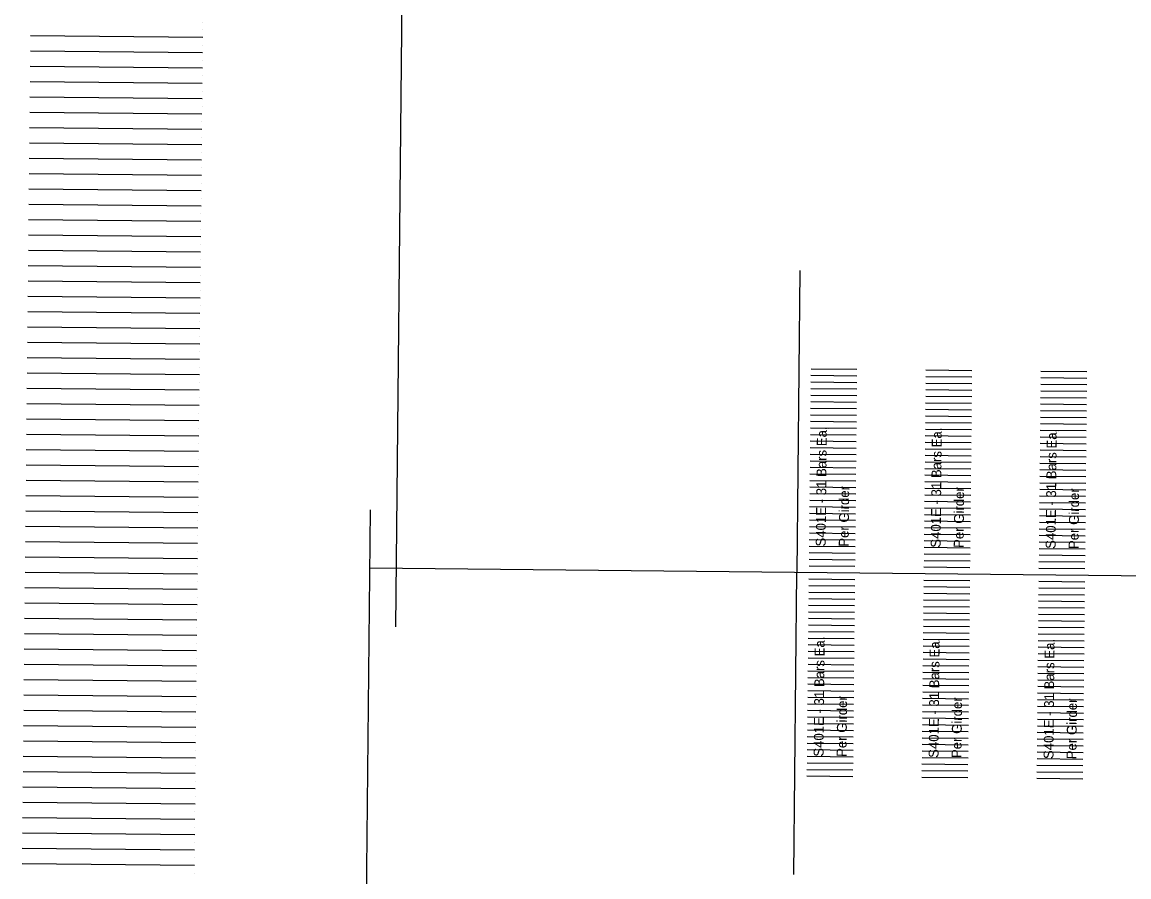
# Model space of a CAD drawing. Extents: x 632547 to 633311, y 380830 to 386139.
# Drawn here: x 633071.5 to 633155.8, y 381137.1 to 381202.2 of the extents above; entities that cross this region are included whole.
import ezdxf

# ---------------------------------------------------------------- set-up
doc = ezdxf.new("R2010")
doc.units = 0
for name, color, linetype in [('B_Border', 7, 'Continuous'), ('R_Border_Scale', 7, 'Continuous'), ('R_Wall', 7, 'Continuous')]:
    doc.layers.add(name, color=color, linetype=linetype)

msp = doc.modelspace()

# ---------------------------------------------------------------- linework, layer by layer
at = {"layer": 'B_Border'}
msp.add_line((633215.055, 381159.402), (633098.001, 381160.586), dxfattribs=at)
at = {"layer": 'R_Border_Scale'}
for p, q in [((633100.563, 381216.118), (633099.956, 381156.121)), ((633085.309, 381202.16), (633085.309, 381202.16)), ((633085.297, 381200.993), (633072.186, 381201.125)), ((633085.297, 381200.993), (633085.297, 381200.993)), ((633085.303, 381201.576), (633085.303, 381201.576)), ((633085.291, 381200.409), (633085.291, 381200.409)), ((633085.286, 381199.825), (633072.174, 381199.958)), ((633085.286, 381199.825), (633085.286, 381199.825)), ((633085.274, 381198.658), (633072.163, 381198.79)), ((633085.274, 381198.658), (633085.274, 381198.658)), ((633085.28, 381199.241), (633085.28, 381199.241)), ((633085.262, 381197.49), (633072.151, 381197.623)), ((633085.268, 381198.074), (633085.268, 381198.074)), ((633085.256, 381196.907), (633085.256, 381196.907)), ((633085.262, 381197.49), (633085.262, 381197.49)), ((633085.25, 381196.323), (633072.139, 381196.456)), ((633085.25, 381196.323), (633085.25, 381196.323)), ((633085.238, 381195.156), (633072.127, 381195.288)), ((633085.238, 381195.156), (633085.238, 381195.156)), ((633085.244, 381195.739), (633085.244, 381195.739)), ((633085.232, 381194.572), (633085.232, 381194.572)), ((633085.226, 381193.988), (633072.115, 381194.121)), ((633085.221, 381193.405), (633085.221, 381193.405)), ((633085.226, 381193.988), (633085.226, 381193.988)), ((633085.215, 381192.821), (633072.103, 381192.954)), ((633085.215, 381192.821), (633085.215, 381192.821)), ((633085.203, 381191.654), (633072.092, 381191.786)), ((633085.209, 381192.237), (633085.209, 381192.237)), ((633085.197, 381191.07), (633085.197, 381191.07)), ((633085.203, 381191.654), (633085.203, 381191.654)), ((633085.191, 381190.486), (633072.08, 381190.619)), ((633085.191, 381190.486), (633085.191, 381190.486)), ((633085.179, 381189.319), (633072.068, 381189.452)), ((633085.179, 381189.319), (633085.179, 381189.319)), ((633085.185, 381189.903), (633085.185, 381189.903)), ((633085.173, 381188.735), (633085.173, 381188.735)), ((633085.167, 381188.152), (633072.056, 381188.284)), ((633085.161, 381187.568), (633085.161, 381187.568)), ((633085.167, 381188.152), (633085.167, 381188.152)), ((633085.156, 381186.984), (633072.044, 381187.117)), ((633085.156, 381186.984), (633085.156, 381186.984)), ((633085.144, 381185.817), (633072.033, 381185.95)), ((633085.144, 381185.817), (633085.144, 381185.817)), ((633085.15, 381186.401), (633085.15, 381186.401)), ((633085.138, 381185.233), (633085.138, 381185.233)), ((633085.132, 381184.65), (633072.021, 381184.782)), ((633085.132, 381184.65), (633085.132, 381184.65)), ((633085.12, 381183.482), (633072.009, 381183.615)), ((633085.12, 381183.482), (633085.12, 381183.482)), ((633085.126, 381184.066), (633085.126, 381184.066)), ((633085.108, 381182.315), (633071.997, 381182.447)), ((633085.114, 381182.898), (633085.114, 381182.898)), ((633130.736, 381183.256), (633130.503, 381160.257)), ((633085.102, 381181.731), (633085.102, 381181.731)), ((633085.108, 381182.315), (633085.108, 381182.315)), ((633085.097, 381181.147), (633071.985, 381181.28)), ((633085.097, 381181.147), (633085.097, 381181.147)), ((633085.085, 381179.98), (633071.974, 381180.113)), ((633085.085, 381179.98), (633085.085, 381179.98)), ((633085.091, 381180.564), (633085.091, 381180.564)), ((633085.079, 381179.396), (633085.079, 381179.396)), ((633085.073, 381178.813), (633071.962, 381178.945)), ((633085.073, 381178.813), (633085.073, 381178.813)), ((633085.061, 381177.645), (633071.95, 381177.778)), ((633085.061, 381177.645), (633085.061, 381177.645)), ((633085.067, 381178.229), (633085.067, 381178.229)), ((633085.049, 381176.478), (633071.938, 381176.611)), ((633085.055, 381177.062), (633085.055, 381177.062)), ((633085.043, 381175.894), (633085.043, 381175.894)), ((633085.049, 381176.478), (633085.049, 381176.478)), ((633135.091, 381175.712), (633131.591, 381175.747)), ((633085.037, 381175.311), (633071.926, 381175.443)), ((633085.037, 381175.311), (633085.037, 381175.311)), ((633135.086, 381175.212), (633131.586, 381175.247)), ((633143.835, 381175.123), (633140.335, 381175.159)), ((633143.84, 381175.623), (633140.341, 381175.659)), ((633152.585, 381175.035), (633149.085, 381175.07)), ((633152.59, 381175.535), (633149.09, 381175.57)), ((633085.026, 381174.143), (633071.915, 381174.276)), ((633085.026, 381174.143), (633085.026, 381174.143)), ((633085.032, 381174.727), (633085.032, 381174.727)), ((633135.076, 381174.212), (633131.576, 381174.247)), ((633135.081, 381174.712), (633131.581, 381174.747)), ((633143.825, 381174.123), (633140.325, 381174.159)), ((633143.83, 381174.623), (633140.33, 381174.659)), ((633152.575, 381174.035), (633149.075, 381174.07)), ((633152.58, 381174.535), (633149.08, 381174.57)), ((633085.02, 381173.56), (633085.02, 381173.56)), ((633135.065, 381173.212), (633131.566, 381173.247)), ((633135.071, 381173.712), (633131.571, 381173.747)), ((633143.82, 381173.623), (633140.32, 381173.659)), ((633152.57, 381173.535), (633149.07, 381173.57)), ((633085.014, 381172.976), (633071.903, 381173.109)), ((633085.008, 381172.392), (633085.008, 381172.392)), ((633085.014, 381172.976), (633085.014, 381172.976)), ((633135.06, 381172.712), (633131.561, 381172.747)), ((633143.81, 381172.623), (633140.31, 381172.659)), ((633143.815, 381173.123), (633140.315, 381173.159)), ((633152.56, 381172.535), (633149.06, 381172.57)), ((633152.565, 381173.035), (633149.065, 381173.07)), ((633085.002, 381171.809), (633071.891, 381171.941)), ((633085.002, 381171.809), (633085.002, 381171.809)), ((633135.05, 381171.712), (633131.55, 381171.747)), ((633135.055, 381172.212), (633131.556, 381172.247)), ((633143.8, 381171.623), (633140.3, 381171.659)), ((633143.805, 381172.123), (633140.305, 381172.159)), ((633152.549, 381171.535), (633149.05, 381171.57)), ((633152.554, 381172.035), (633149.055, 381172.07)), ((633084.99, 381170.641), (633071.879, 381170.774)), ((633084.996, 381171.225), (633084.996, 381171.225)), ((633135.04, 381170.712), (633131.54, 381170.747)), ((633135.045, 381171.212), (633131.545, 381171.247)), ((633143.79, 381170.623), (633140.29, 381170.659)), ((633143.795, 381171.123), (633140.295, 381171.159)), ((633152.544, 381171.035), (633149.045, 381171.07)), ((633084.984, 381170.058), (633084.984, 381170.058)), ((633084.99, 381170.641), (633084.99, 381170.641)), ((633135.035, 381170.212), (633131.535, 381170.247)), ((633143.785, 381170.123), (633140.285, 381170.159)), ((633152.534, 381170.035), (633149.034, 381170.07)), ((633152.539, 381170.535), (633149.039, 381170.57)), ((633084.978, 381169.474), (633071.867, 381169.607)), ((633084.978, 381169.474), (633084.978, 381169.474)), ((633135.025, 381169.212), (633131.525, 381169.247)), ((633135.03, 381169.712), (633131.53, 381169.747)), ((633143.775, 381169.123), (633140.275, 381169.159)), ((633143.78, 381169.623), (633140.28, 381169.659)), ((633152.524, 381169.035), (633149.024, 381169.07)), ((633152.529, 381169.535), (633149.029, 381169.57)), ((633084.967, 381168.307), (633071.855, 381168.439)), ((633084.967, 381168.307), (633084.967, 381168.307)), ((633084.973, 381168.89), (633084.973, 381168.89)), ((633135.015, 381168.212), (633131.515, 381168.247)), ((633135.02, 381168.712), (633131.52, 381168.747)), ((633143.764, 381168.123), (633140.265, 381168.159)), ((633143.77, 381168.623), (633140.27, 381168.659)), ((633152.519, 381168.535), (633149.019, 381168.57)), ((633084.961, 381167.723), (633084.961, 381167.723)), ((633135.01, 381167.712), (633131.51, 381167.747)), ((633143.759, 381167.624), (633140.26, 381167.659)), ((633152.509, 381167.535), (633149.009, 381167.57)), ((633152.514, 381168.035), (633149.014, 381168.07)), ((633084.955, 381167.139), (633071.844, 381167.272)), ((633084.949, 381166.556), (633084.949, 381166.556)), ((633084.955, 381167.139), (633084.955, 381167.139)), ((633135, 381166.712), (633131.5, 381166.748)), ((633135.005, 381167.212), (633131.505, 381167.247)), ((633143.749, 381166.624), (633140.249, 381166.659)), ((633143.754, 381167.124), (633140.255, 381167.159)), ((633152.499, 381166.535), (633148.999, 381166.57)), ((633152.504, 381167.035), (633149.004, 381167.07)), ((633084.943, 381165.972), (633071.832, 381166.104)), ((633084.943, 381165.972), (633084.943, 381165.972)), ((633134.99, 381165.712), (633131.49, 381165.748)), ((633134.995, 381166.212), (633131.495, 381166.248)), ((633143.739, 381165.624), (633140.239, 381165.659)), ((633143.744, 381166.124), (633140.244, 381166.159)), ((633152.494, 381166.035), (633148.994, 381166.07)), ((633084.931, 381164.804), (633071.82, 381164.937)), ((633084.931, 381164.804), (633084.931, 381164.804)), ((633084.937, 381165.388), (633084.937, 381165.388)), ((633098.046, 381165.03), (633097.439, 381105.033)), ((633134.985, 381165.212), (633131.485, 381165.248)), ((633143.734, 381165.124), (633140.234, 381165.159)), ((633152.484, 381165.035), (633148.984, 381165.071)), ((633152.489, 381165.535), (633148.989, 381165.571)), ((633084.925, 381164.221), (633084.925, 381164.221)), ((633134.974, 381164.212), (633131.475, 381164.248)), ((633134.979, 381164.712), (633131.48, 381164.748)), ((633143.724, 381164.124), (633140.224, 381164.159)), ((633143.729, 381164.624), (633140.229, 381164.659)), ((633152.474, 381164.035), (633148.974, 381164.071)), ((633152.479, 381164.535), (633148.979, 381164.571)), ((633084.919, 381163.637), (633071.808, 381163.77)), ((633084.919, 381163.637), (633084.919, 381163.637)), ((633134.964, 381163.212), (633131.464, 381163.248)), ((633134.969, 381163.712), (633131.47, 381163.748)), ((633143.714, 381163.124), (633140.214, 381163.159)), ((633143.719, 381163.624), (633140.219, 381163.659)), ((633152.463, 381163.035), (633148.964, 381163.071)), ((633152.468, 381163.535), (633148.969, 381163.571)), ((633084.908, 381162.47), (633071.796, 381162.602)), ((633084.908, 381162.47), (633084.908, 381162.47)), ((633084.913, 381163.053), (633084.913, 381163.053)), ((633134.954, 381162.212), (633131.454, 381162.248)), ((633134.959, 381162.712), (633131.459, 381162.748)), ((633143.709, 381162.624), (633140.209, 381162.659)), ((633152.458, 381162.535), (633148.959, 381162.571)), ((633084.896, 381161.302), (633071.785, 381161.435)), ((633084.902, 381161.886), (633084.902, 381161.886)), ((633134.949, 381161.712), (633131.449, 381161.748)), ((633143.699, 381161.624), (633140.199, 381161.659)), ((633143.704, 381162.124), (633140.204, 381162.159)), ((633152.448, 381161.535), (633148.948, 381161.571)), ((633152.453, 381162.035), (633148.953, 381162.071)), ((633084.89, 381160.719), (633084.89, 381160.719)), ((633084.896, 381161.302), (633084.896, 381161.302)), ((633134.939, 381160.712), (633131.439, 381160.748)), ((633134.944, 381161.212), (633131.444, 381161.248)), ((633143.689, 381160.624), (633140.189, 381160.659)), ((633143.694, 381161.124), (633140.194, 381161.159)), ((633152.438, 381160.535), (633148.938, 381160.571)), ((633152.443, 381161.035), (633148.943, 381161.071)), ((633084.884, 381160.135), (633071.773, 381160.268)), ((633084.884, 381160.135), (633084.884, 381160.135)), ((633130.271, 381137.258), (633130.503, 381160.257)), ((633134.929, 381159.712), (633131.429, 381159.748)), ((633084.872, 381158.968), (633071.761, 381159.1)), ((633084.872, 381158.968), (633084.872, 381158.968)), ((633084.878, 381159.551), (633084.878, 381159.551)), ((633134.924, 381159.212), (633131.424, 381159.248)), ((633143.673, 381159.124), (633140.174, 381159.159)), ((633143.678, 381159.624), (633140.179, 381159.659)), ((633152.423, 381159.035), (633148.923, 381159.071)), ((633152.428, 381159.535), (633148.928, 381159.571)), ((633084.866, 381158.384), (633084.866, 381158.384)), ((633134.914, 381158.213), (633131.414, 381158.248)), ((633134.919, 381158.713), (633131.419, 381158.748)), ((633143.663, 381158.124), (633140.163, 381158.159)), ((633143.668, 381158.624), (633140.169, 381158.659)), ((633152.413, 381158.035), (633148.913, 381158.071)), ((633152.418, 381158.535), (633148.918, 381158.571)), ((633084.86, 381157.8), (633071.749, 381157.933)), ((633084.854, 381157.217), (633084.854, 381157.217)), ((633084.86, 381157.8), (633084.86, 381157.8)), ((633134.904, 381157.213), (633131.404, 381157.248)), ((633134.909, 381157.713), (633131.409, 381157.748)), ((633143.658, 381157.624), (633140.158, 381157.659)), ((633152.408, 381157.536), (633148.908, 381157.571)), ((633084.849, 381156.633), (633071.737, 381156.766)), ((633084.849, 381156.633), (633084.849, 381156.633)), ((633134.899, 381156.713), (633131.399, 381156.748)), ((633143.648, 381156.624), (633140.148, 381156.659)), ((633143.653, 381157.124), (633140.153, 381157.159)), ((633152.398, 381156.536), (633148.898, 381156.571)), ((633152.403, 381157.036), (633148.903, 381157.071)), ((633084.837, 381155.466), (633071.726, 381155.598)), ((633084.843, 381156.049), (633084.843, 381156.049)), ((633134.888, 381155.713), (633131.389, 381155.748)), ((633134.893, 381156.213), (633131.394, 381156.248)), ((633143.638, 381155.624), (633140.138, 381155.66)), ((633143.643, 381156.124), (633140.143, 381156.16)), ((633152.388, 381155.536), (633148.888, 381155.571)), ((633152.393, 381156.036), (633148.893, 381156.071)), ((633084.831, 381154.882), (633084.831, 381154.882)), ((633084.837, 381155.466), (633084.837, 381155.466)), ((633134.878, 381154.713), (633131.379, 381154.748)), ((633134.883, 381155.213), (633131.384, 381155.248)), ((633143.628, 381154.624), (633140.128, 381154.66)), ((633143.633, 381155.124), (633140.133, 381155.16)), ((633152.382, 381155.036), (633148.883, 381155.071)), ((633084.825, 381154.298), (633071.714, 381154.431)), ((633084.825, 381154.298), (633084.825, 381154.298)), ((633134.873, 381154.213), (633131.373, 381154.248)), ((633143.623, 381154.124), (633140.123, 381154.16)), ((633152.372, 381154.036), (633148.873, 381154.071)), ((633152.377, 381154.536), (633148.878, 381154.571)), ((633084.813, 381153.131), (633071.702, 381153.264)), ((633084.813, 381153.131), (633084.813, 381153.131)), ((633084.819, 381153.715), (633084.819, 381153.715)), ((633134.863, 381153.213), (633131.363, 381153.248)), ((633134.868, 381153.713), (633131.368, 381153.748)), ((633143.613, 381153.124), (633140.113, 381153.16)), ((633143.618, 381153.624), (633140.118, 381153.66)), ((633152.362, 381153.036), (633148.862, 381153.071)), ((633152.367, 381153.536), (633148.867, 381153.571)), ((633084.807, 381152.547), (633084.807, 381152.547)), ((633134.853, 381152.213), (633131.353, 381152.248)), ((633134.858, 381152.713), (633131.358, 381152.748)), ((633143.603, 381152.124), (633140.103, 381152.16)), ((633143.608, 381152.624), (633140.108, 381152.66)), ((633152.357, 381152.536), (633148.857, 381152.571)), ((633084.801, 381151.964), (633071.69, 381152.096)), ((633084.795, 381151.38), (633084.795, 381151.38)), ((633084.801, 381151.964), (633084.801, 381151.964)), ((633134.848, 381151.713), (633131.348, 381151.748)), ((633143.598, 381151.624), (633140.098, 381151.66)), ((633152.347, 381151.536), (633148.847, 381151.571)), ((633152.352, 381152.036), (633148.852, 381152.071)), ((633084.789, 381150.796), (633071.678, 381150.929)), ((633084.789, 381150.796), (633084.789, 381150.796)), ((633134.838, 381150.713), (633131.338, 381150.748)), ((633134.843, 381151.213), (633131.343, 381151.248)), ((633143.587, 381150.624), (633140.088, 381150.66)), ((633143.592, 381151.124), (633140.093, 381151.16)), ((633152.337, 381150.536), (633148.837, 381150.571)), ((633152.342, 381151.036), (633148.842, 381151.071)), ((633084.778, 381149.629), (633071.667, 381149.761)), ((633084.778, 381149.629), (633084.778, 381149.629)), ((633084.784, 381150.213), (633084.784, 381150.213)), ((633134.828, 381149.713), (633131.328, 381149.748)), ((633134.833, 381150.213), (633131.333, 381150.248)), ((633143.577, 381149.624), (633140.077, 381149.66)), ((633143.582, 381150.124), (633140.083, 381150.16)), ((633152.332, 381150.036), (633148.832, 381150.071)), ((633084.772, 381149.045), (633084.772, 381149.045)), ((633134.818, 381148.713), (633131.318, 381148.748)), ((633134.823, 381149.213), (633131.323, 381149.248)), ((633143.572, 381149.124), (633140.072, 381149.16)), ((633152.322, 381149.036), (633148.822, 381149.071)), ((633152.327, 381149.536), (633148.827, 381149.571)), ((633084.766, 381148.461), (633071.655, 381148.594)), ((633084.766, 381148.461), (633084.766, 381148.461)), ((633134.813, 381148.213), (633131.313, 381148.248)), ((633143.562, 381148.125), (633140.062, 381148.16)), ((633143.567, 381148.624), (633140.067, 381148.66)), ((633152.312, 381148.036), (633148.812, 381148.071)), ((633152.317, 381148.536), (633148.817, 381148.571)), ((633084.754, 381147.294), (633071.643, 381147.427)), ((633084.754, 381147.294), (633084.754, 381147.294)), ((633084.76, 381147.878), (633084.76, 381147.878)), ((633134.802, 381147.213), (633131.303, 381147.248)), ((633134.808, 381147.713), (633131.308, 381147.748)), ((633143.552, 381147.125), (633140.052, 381147.16)), ((633143.557, 381147.625), (633140.057, 381147.66)), ((633152.302, 381147.036), (633148.802, 381147.071)), ((633152.307, 381147.536), (633148.807, 381147.571)), ((633084.742, 381146.127), (633071.631, 381146.259)), ((633084.748, 381146.71), (633084.748, 381146.71)), ((633134.792, 381146.213), (633131.293, 381146.249)), ((633134.797, 381146.713), (633131.298, 381146.749)), ((633143.547, 381146.625), (633140.047, 381146.66)), ((633152.296, 381146.536), (633148.797, 381146.571)), ((633084.736, 381145.543), (633084.736, 381145.543)), ((633084.742, 381146.127), (633084.742, 381146.127)), ((633134.787, 381145.713), (633131.287, 381145.749)), ((633143.537, 381145.625), (633140.037, 381145.66)), ((633143.542, 381146.125), (633140.042, 381146.16)), ((633152.286, 381145.536), (633148.787, 381145.572)), ((633152.291, 381146.036), (633148.792, 381146.072)), ((633084.73, 381144.959), (633071.619, 381145.092)), ((633084.73, 381144.959), (633084.73, 381144.959)), ((633134.777, 381144.713), (633131.277, 381144.749)), ((633134.782, 381145.213), (633131.282, 381145.249)), ((633143.527, 381144.625), (633140.027, 381144.66)), ((633143.532, 381145.125), (633140.032, 381145.16)), ((633152.276, 381144.536), (633148.776, 381144.572)), ((633152.281, 381145.036), (633148.782, 381145.072)), ((633084.719, 381143.792), (633071.607, 381143.925)), ((633084.719, 381143.792), (633084.719, 381143.792)), ((633084.725, 381144.376), (633084.725, 381144.376)), ((633084.713, 381143.208), (633084.713, 381143.208)), ((633084.707, 381142.625), (633071.596, 381142.757)), ((633084.701, 381142.041), (633084.701, 381142.041)), ((633084.707, 381142.625), (633084.707, 381142.625)), ((633084.695, 381141.457), (633071.584, 381141.59)), ((633084.695, 381141.457), (633084.695, 381141.457)), ((633084.683, 381140.29), (633071.572, 381140.423)), ((633084.689, 381140.874), (633084.689, 381140.874)), ((633084.677, 381139.706), (633084.677, 381139.706)), ((633084.683, 381140.29), (633084.683, 381140.29)), ((633084.671, 381139.123), (633071.56, 381139.255)), ((633084.671, 381139.123), (633084.671, 381139.123)), ((633084.66, 381137.955), (633071.548, 381138.088)), ((633084.66, 381137.955), (633084.66, 381137.955)), ((633084.665, 381138.539), (633084.665, 381138.539)), ((633084.654, 381137.372), (633084.654, 381137.372))]:
    msp.add_line(p, q, dxfattribs=at)

# ---------------------------------------------------------------- texts
at = {"layer": 'R_Wall'}
for s, p in [('S401E - 31 Bars Ea,', (633132.704, 381162.235)), ('S401E - 31 Bars Ea,', (633141.454, 381162.146)), ('S401E - 31 Bars Ea,', (633150.203, 381162.058)), ('Per Girder', (633134.454, 381162.218)), ('Per Girder', (633143.204, 381162.129)), ('Per Girder', (633151.953, 381162.041)), ('S401E - 31 Bars Ea,', (633132.542, 381146.236)), ('S401E - 31 Bars Ea,', (633141.292, 381146.147)), ('S401E - 31 Bars Ea,', (633150.042, 381146.059)), ('Per Girder', (633134.292, 381146.218)), ('Per Girder', (633143.042, 381146.13)), ('Per Girder', (633151.791, 381146.041))]:
    msp.add_text(s, height=0.75, rotation=89.43036, dxfattribs=at).set_placement(p)

doc.saveas('drawing.dxf')
